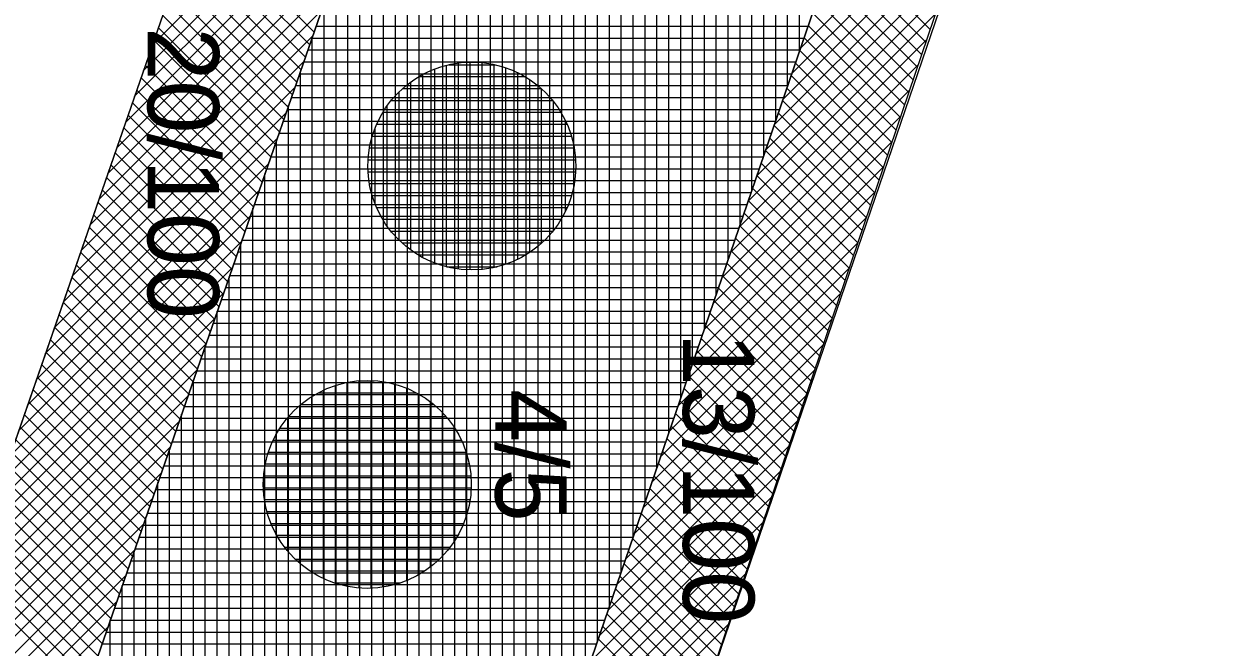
# Model space of a CAD drawing. Extents: x -565346 to -564154, y -1097386 to -1095620.
# Drawn here: x -564216.58 to -564196.4, y -1096400.96 to -1096390.47 of the extents above; entities that cross this region are included whole.
import ezdxf

# ---------------------------------------------------------------- set-up
doc = ezdxf.new("R2010")
doc.units = 0
for name, color, linetype in [('Vrstva 1', 7, 'Continuous'), ('Vrstva 13', 7, 'Continuous'), ('Vrstva 40', 7, 'Continuous'), ('Vrstva 41', 7, 'Continuous'), ('Vrstva 42', 7, 'Continuous'), ('Vrstva 43', 7, 'Continuous'), ('Vrstva 44', 7, 'Continuous')]:
    doc.layers.add(name, color=color, linetype=linetype)

msp = doc.modelspace()

# ---------------------------------------------------------------- linework, layer by layer
at = {"layer": 'Vrstva 1'}
msp.add_line((-564183.37, -1096301.17), (-564225.11, -1096421.68), dxfattribs=at)
at = {"layer": 'Vrstva 13'}
msp.add_line((-564171.03, -1096302.15), (-564215.39, -1096431.76), dxfattribs=at)
at = {"layer": 'Vrstva 41'}
for points in [[(-564215.226, -1096425.104), (-564213.26, -1096425.74), (-564190.01, -1096357.19), (-564171.03, -1096302.15), (-564177.55, -1096264.11), (-564190.98, -1096227.75), (-564194.264, -1096223.181), (-564195.888, -1096224.348), (-564192.762, -1096228.697), (-564179.49, -1096264.63), (-564173.087, -1096301.985)], [(-564225.11, -1096421.68), (-564222.748, -1096422.498), (-564180.797, -1096301.38), (-564186.765, -1096266.582), (-564199.442, -1096232.246), (-564201.974, -1096228.723), (-564204.005, -1096230.182), (-564201.67, -1096233.43), (-564189.19, -1096267.23), (-564183.37, -1096301.17)]]:
    msp.add_lwpolyline(points, close=True, dxfattribs=at)
at = {"layer": 'Vrstva 42'}
for p, q in [((-564210.378, -1096386.783), (-564214.425, -1096390.83)), ((-564210.527, -1096387.216), (-564214.575, -1096391.263)), ((-564210.677, -1096387.649), (-564214.725, -1096391.696)), ((-564200.371, -1096387.737), (-564203.512, -1096390.878)), ((-564210.827, -1096388.081), (-564214.875, -1096392.129)), ((-564200.516, -1096388.165), (-564203.659, -1096391.308)), ((-564210.977, -1096388.514), (-564215.024, -1096392.561)), ((-564213.667, -1096388.643), (-564211.702, -1096390.608)), ((-564200.661, -1096388.593), (-564203.806, -1096391.738)), ((-564213.74, -1096388.853), (-564211.775, -1096390.818)), ((-564211.127, -1096388.947), (-564215.174, -1096392.994)), ((-564213.813, -1096389.063), (-564211.848, -1096391.028)), ((-564200.806, -1096389.021), (-564203.953, -1096392.168)), ((-564202.877, -1096389.023), (-564201.331, -1096390.568)), ((-564202.949, -1096389.233), (-564201.403, -1096390.78)), ((-564211.277, -1096389.379), (-564215.324, -1096393.427)), ((-564213.886, -1096389.273), (-564211.921, -1096391.238)), ((-564200.951, -1096389.449), (-564204.101, -1096392.598)), ((-564203.021, -1096389.444), (-564201.474, -1096390.991)), ((-564213.958, -1096389.483), (-564211.993, -1096391.448)), ((-564203.093, -1096389.655), (-564201.546, -1096391.202)), ((-564211.427, -1096389.812), (-564215.474, -1096393.859)), ((-564214.031, -1096389.693), (-564212.066, -1096391.658)), ((-564201.096, -1096389.877), (-564204.248, -1096393.028)), ((-564203.165, -1096389.865), (-564201.617, -1096391.413)), ((-564214.104, -1096389.903), (-564212.139, -1096391.868)), ((-564203.237, -1096390.076), (-564201.689, -1096391.624)), ((-564211.577, -1096390.245), (-564215.624, -1096394.292)), ((-564214.177, -1096390.113), (-564212.212, -1096392.078)), ((-564214.249, -1096390.323), (-564212.284, -1096392.288)), ((-564201.242, -1096390.305), (-564204.395, -1096393.458)), ((-564203.309, -1096390.287), (-564201.761, -1096391.836)), ((-564211.727, -1096390.678), (-564215.774, -1096394.725)), ((-564214.322, -1096390.534), (-564212.357, -1096392.498)), ((-564203.382, -1096390.498), (-564201.832, -1096392.047)), ((-564214.395, -1096390.744), (-564212.43, -1096392.709)), ((-564201.387, -1096390.733), (-564204.542, -1096393.889)), ((-564203.454, -1096390.708), (-564201.904, -1096392.258)), ((-564214.468, -1096390.954), (-564212.503, -1096392.919)), ((-564203.526, -1096390.919), (-564201.976, -1096392.469)), ((-564211.876, -1096391.11), (-564215.924, -1096395.158)), ((-564214.54, -1096391.164), (-564212.576, -1096393.129)), ((-564201.532, -1096391.161), (-564204.689, -1096394.319)), ((-564203.598, -1096391.13), (-564202.047, -1096392.68)), ((-564214.613, -1096391.374), (-564212.648, -1096393.339)), ((-564203.67, -1096391.341), (-564202.119, -1096392.892)), ((-564212.026, -1096391.543), (-564216.074, -1096395.59)), ((-564214.686, -1096391.584), (-564212.721, -1096393.549)), ((-564201.677, -1096391.589), (-564204.836, -1096394.749)), ((-564203.742, -1096391.551), (-564202.191, -1096393.103)), ((-564214.759, -1096391.794), (-564212.794, -1096393.759)), ((-564203.814, -1096391.762), (-564202.262, -1096393.314)), ((-564212.176, -1096391.976), (-564216.223, -1096396.023)), ((-564214.831, -1096392.004), (-564212.867, -1096393.969)), ((-564201.822, -1096392.017), (-564204.984, -1096395.179)), ((-564203.886, -1096391.973), (-564202.334, -1096393.525)), ((-564214.904, -1096392.214), (-564212.939, -1096394.179)), ((-564203.959, -1096392.183), (-564202.405, -1096393.737)), ((-564212.326, -1096392.408), (-564216.373, -1096396.456)), ((-564214.977, -1096392.424), (-564213.012, -1096394.389)), ((-564201.967, -1096392.445), (-564205.131, -1096395.609)), ((-564204.031, -1096392.394), (-564202.477, -1096393.948)), ((-564215.05, -1096392.634), (-564213.085, -1096394.599)), ((-564204.103, -1096392.605), (-564202.549, -1096394.159)), ((-564212.476, -1096392.841), (-564216.523, -1096396.888)), ((-564215.122, -1096392.844), (-564213.158, -1096394.809)), ((-564202.113, -1096392.873), (-564205.278, -1096396.039)), ((-564204.175, -1096392.816), (-564202.62, -1096394.37)), ((-564215.195, -1096393.055), (-564213.23, -1096395.019)), ((-564204.247, -1096393.026), (-564202.692, -1096394.581)), ((-564212.626, -1096393.274), (-564216.673, -1096397.321)), ((-564215.268, -1096393.265), (-564213.303, -1096395.229)), ((-564202.258, -1096393.301), (-564205.425, -1096396.469)), ((-564204.319, -1096393.237), (-564202.764, -1096394.793)), ((-564215.341, -1096393.475), (-564213.376, -1096395.44)), ((-564204.391, -1096393.448), (-564202.835, -1096395.004)), ((-564212.776, -1096393.707), (-564216.823, -1096397.754)), ((-564215.414, -1096393.685), (-564213.449, -1096395.65)), ((-564204.463, -1096393.658), (-564202.907, -1096395.215)), ((-564215.486, -1096393.895), (-564213.521, -1096395.86)), ((-564202.403, -1096393.729), (-564205.572, -1096396.899)), ((-564204.535, -1096393.869), (-564202.979, -1096395.426)), ((-564215.559, -1096394.105), (-564213.594, -1096396.07)), ((-564204.608, -1096394.08), (-564203.05, -1096395.637)), ((-564212.926, -1096394.139), (-564216.973, -1096398.187)), ((-564215.632, -1096394.315), (-564213.667, -1096396.28)), ((-564202.548, -1096394.157), (-564205.72, -1096397.329)), ((-564204.68, -1096394.291), (-564203.122, -1096395.849)), ((-564204.752, -1096394.501), (-564203.193, -1096396.06)), ((-564213.075, -1096394.572), (-564217.123, -1096398.619)), ((-564215.705, -1096394.525), (-564213.74, -1096396.49)), ((-564202.693, -1096394.585), (-564205.867, -1096397.759)), ((-564204.824, -1096394.712), (-564203.265, -1096396.271)), ((-564215.777, -1096394.735), (-564213.812, -1096396.7)), ((-564213.225, -1096395.005), (-564217.273, -1096399.052)), ((-564215.85, -1096394.945), (-564213.885, -1096396.91)), ((-564202.838, -1096395.013), (-564206.014, -1096398.189)), ((-564204.896, -1096394.923), (-564203.337, -1096396.482)), ((-564215.923, -1096395.155), (-564213.958, -1096397.12)), ((-564204.968, -1096395.134), (-564203.408, -1096396.693)), ((-564213.375, -1096395.438), (-564217.422, -1096399.485)), ((-564215.996, -1096395.365), (-564214.031, -1096397.33)), ((-564202.984, -1096395.441), (-564206.161, -1096398.619)), ((-564205.04, -1096395.344), (-564203.48, -1096396.905)), ((-564216.068, -1096395.575), (-564214.104, -1096397.54)), ((-564205.112, -1096395.555), (-564203.552, -1096397.116)), ((-564213.525, -1096395.87), (-564217.572, -1096399.917)), ((-564216.141, -1096395.786), (-564214.176, -1096397.75)), ((-564203.129, -1096395.869), (-564206.308, -1096399.049)), ((-564205.185, -1096395.766), (-564203.623, -1096397.327)), ((-564216.214, -1096395.996), (-564214.249, -1096397.96)), ((-564205.257, -1096395.976), (-564203.695, -1096397.538)), ((-564213.675, -1096396.303), (-564217.722, -1096400.35)), ((-564216.287, -1096396.206), (-564214.322, -1096398.171)), ((-564203.274, -1096396.297), (-564206.455, -1096399.479)), ((-564205.329, -1096396.187), (-564203.766, -1096397.749)), ((-564216.359, -1096396.416), (-564214.395, -1096398.381)), ((-564205.401, -1096396.398), (-564203.838, -1096397.961)), ((-564213.825, -1096396.736), (-564217.872, -1096400.783)), ((-564216.432, -1096396.626), (-564214.467, -1096398.591)), ((-564203.419, -1096396.725), (-564206.603, -1096399.909)), ((-564205.473, -1096396.609), (-564203.91, -1096398.172)), ((-564216.505, -1096396.836), (-564214.54, -1096398.801)), ((-564205.545, -1096396.819), (-564203.981, -1096398.383)), ((-564216.578, -1096397.046), (-564214.613, -1096399.011)), ((-564205.617, -1096397.03), (-564204.053, -1096398.594)), ((-564213.975, -1096397.168), (-564218.022, -1096401.216)), ((-564216.651, -1096397.256), (-564214.686, -1096399.221)), ((-564203.564, -1096397.153), (-564206.75, -1096400.339)), ((-564205.689, -1096397.241), (-564204.125, -1096398.806)), ((-564216.723, -1096397.466), (-564214.758, -1096399.431)), ((-564205.762, -1096397.451), (-564204.196, -1096399.017)), ((-564214.125, -1096397.601), (-564218.172, -1096401.648)), ((-564216.796, -1096397.676), (-564214.831, -1096399.641)), ((-564203.709, -1096397.581), (-564206.897, -1096400.769)), ((-564205.834, -1096397.662), (-564204.268, -1096399.228)), ((-564216.869, -1096397.886), (-564214.904, -1096399.851)), ((-564205.906, -1096397.873), (-564204.34, -1096399.439)), ((-564214.274, -1096398.034), (-564218.322, -1096402.081)), ((-564216.942, -1096398.096), (-564214.977, -1096400.061)), ((-564203.855, -1096398.009), (-564207.044, -1096401.199)), ((-564205.978, -1096398.084), (-564204.411, -1096399.65)), ((-564217.014, -1096398.307), (-564215.049, -1096400.271)), ((-564206.05, -1096398.294), (-564204.483, -1096399.862)), ((-564214.424, -1096398.467), (-564218.472, -1096402.514)), ((-564217.087, -1096398.517), (-564215.122, -1096400.481)), ((-564204, -1096398.437), (-564207.191, -1096401.629)), ((-564206.122, -1096398.505), (-564204.554, -1096400.073)), ((-564217.16, -1096398.727), (-564215.195, -1096400.692)), ((-564206.194, -1096398.716), (-564204.626, -1096400.284)), ((-564214.574, -1096398.899), (-564218.621, -1096402.947)), ((-564217.233, -1096398.937), (-564215.268, -1096400.902)), ((-564204.145, -1096398.865), (-564207.339, -1096402.059)), ((-564206.266, -1096398.926), (-564204.698, -1096400.495)), ((-564217.305, -1096399.147), (-564215.341, -1096401.112)), ((-564206.339, -1096399.137), (-564204.769, -1096400.706)), ((-564214.724, -1096399.332), (-564218.771, -1096403.379)), ((-564217.378, -1096399.357), (-564215.413, -1096401.322)), ((-564204.29, -1096399.293), (-564207.486, -1096402.489)), ((-564206.411, -1096399.348), (-564204.841, -1096400.918)), ((-564206.483, -1096399.559), (-564204.913, -1096401.129)), ((-564214.874, -1096399.765), (-564218.921, -1096403.812)), ((-564217.451, -1096399.567), (-564215.486, -1096401.532)), ((-564204.435, -1096399.721), (-564207.633, -1096402.919)), ((-564217.524, -1096399.777), (-564215.559, -1096401.742)), ((-564206.555, -1096399.769), (-564204.984, -1096401.34)), ((-564204.58, -1096400.149), (-564207.78, -1096403.349)), ((-564206.627, -1096399.98), (-564205.056, -1096401.551)), ((-564215.024, -1096400.198), (-564219.071, -1096404.245)), ((-564206.699, -1096400.191), (-564205.128, -1096401.762)), ((-564206.771, -1096400.402), (-564205.199, -1096401.974)), ((-564215.174, -1096400.63), (-564219.221, -1096404.677)), ((-564204.726, -1096400.577), (-564207.927, -1096403.779)), ((-564206.843, -1096400.612), (-564205.271, -1096402.185)), ((-564206.916, -1096400.823), (-564205.342, -1096402.396))]:
    msp.add_line(p, q, dxfattribs=at)
at = {"layer": 'Vrstva 43'}
for p, q in [((-564203.53, -1096390.931), (-564203.53, -1096367.013)), ((-564203.73, -1096391.516), (-564203.73, -1096367.591)), ((-564203.93, -1096392.1), (-564203.93, -1096368.168)), ((-564204.13, -1096392.684), (-564204.13, -1096368.745)), ((-564204.33, -1096393.269), (-564204.33, -1096369.323)), ((-564204.53, -1096393.853), (-564204.53, -1096369.9)), ((-564204.73, -1096394.437), (-564204.73, -1096370.478)), ((-564204.93, -1096395.022), (-564204.93, -1096371.055)), ((-564205.13, -1096395.606), (-564205.13, -1096371.633)), ((-564205.33, -1096396.191), (-564205.33, -1096372.21)), ((-564205.53, -1096396.775), (-564205.53, -1096372.787)), ((-564205.73, -1096397.359), (-564205.73, -1096373.365)), ((-564205.93, -1096397.944), (-564205.93, -1096373.942)), ((-564206.13, -1096398.528), (-564206.13, -1096374.52)), ((-564206.33, -1096399.112), (-564206.33, -1096375.097)), ((-564206.53, -1096399.697), (-564206.53, -1096375.675)), ((-564206.73, -1096400.281), (-564206.73, -1096376.252)), ((-564206.93, -1096400.865), (-564206.93, -1096376.829)), ((-564207.13, -1096401.45), (-564207.13, -1096377.407)), ((-564207.33, -1096402.034), (-564207.33, -1096377.984)), ((-564207.53, -1096402.618), (-564207.53, -1096378.562)), ((-564207.73, -1096403.203), (-564207.73, -1096379.139)), ((-564207.93, -1096403.787), (-564207.93, -1096379.717)), ((-564208.13, -1096404.371), (-564208.13, -1096380.294)), ((-564208.33, -1096404.956), (-564208.33, -1096380.871)), ((-564208.53, -1096405.54), (-564208.53, -1096381.449)), ((-564208.73, -1096406.124), (-564208.73, -1096382.026)), ((-564208.93, -1096406.709), (-564208.93, -1096382.604)), ((-564209.13, -1096407.293), (-564209.13, -1096383.181)), ((-564209.33, -1096407.877), (-564209.33, -1096383.758)), ((-564209.53, -1096408.462), (-564209.53, -1096384.336)), ((-564209.73, -1096409.046), (-564209.73, -1096384.913)), ((-564209.93, -1096409.63), (-564209.93, -1096385.491)), ((-564210.13, -1096410.215), (-564210.13, -1096386.068)), ((-564210.33, -1096410.799), (-564210.33, -1096386.646)), ((-564210.53, -1096411.384), (-564210.53, -1096387.223)), ((-564210.73, -1096411.968), (-564210.73, -1096387.8)), ((-564210.93, -1096412.552), (-564210.93, -1096388.378)), ((-564211.13, -1096413.137), (-564211.13, -1096388.955)), ((-564211.33, -1096413.721), (-564211.33, -1096389.533)), ((-564211.53, -1096414.305), (-564211.53, -1096390.11)), ((-564211.668, -1096390.51), (-564203.386, -1096390.51)), ((-564211.738, -1096390.71), (-564203.454, -1096390.71)), ((-564211.73, -1096414.89), (-564211.73, -1096390.688)), ((-564211.807, -1096390.91), (-564203.523, -1096390.91)), ((-564211.93, -1096415.474), (-564211.93, -1096391.265)), ((-564211.876, -1096391.11), (-564203.591, -1096391.11)), ((-564211.946, -1096391.31), (-564203.66, -1096391.31)), ((-564212.015, -1096391.51), (-564203.728, -1096391.51)), ((-564212.13, -1096416.058), (-564212.13, -1096391.842)), ((-564212.084, -1096391.71), (-564203.796, -1096391.71)), ((-564212.153, -1096391.91), (-564203.865, -1096391.91)), ((-564212.223, -1096392.11), (-564203.933, -1096392.11)), ((-564212.33, -1096416.643), (-564212.33, -1096392.42)), ((-564212.292, -1096392.31), (-564204.002, -1096392.31)), ((-564212.361, -1096392.51), (-564204.07, -1096392.51)), ((-564212.43, -1096392.71), (-564204.139, -1096392.71)), ((-564212.53, -1096417.227), (-564212.53, -1096392.997)), ((-564212.5, -1096392.91), (-564204.207, -1096392.91)), ((-564212.569, -1096393.11), (-564204.276, -1096393.11)), ((-564212.638, -1096393.31), (-564204.344, -1096393.31)), ((-564212.777, -1096393.71), (-564204.481, -1096393.71)), ((-564212.73, -1096417.811), (-564212.73, -1096393.575)), ((-564212.708, -1096393.51), (-564204.413, -1096393.51)), ((-564212.846, -1096393.91), (-564204.549, -1096393.91)), ((-564212.915, -1096394.11), (-564204.618, -1096394.11)), ((-564212.985, -1096394.31), (-564204.686, -1096394.31)), ((-564212.93, -1096418.396), (-564212.93, -1096394.152)), ((-564213.054, -1096394.51), (-564204.755, -1096394.51)), ((-564213.123, -1096394.71), (-564204.823, -1096394.71)), ((-564213.192, -1096394.91), (-564204.892, -1096394.91)), ((-564213.13, -1096418.98), (-564213.13, -1096394.73)), ((-564213.262, -1096395.11), (-564204.96, -1096395.11)), ((-564213.331, -1096395.31), (-564205.029, -1096395.31)), ((-564213.33, -1096419.564), (-564213.33, -1096395.307)), ((-564213.4, -1096395.51), (-564205.097, -1096395.51)), ((-564213.47, -1096395.71), (-564205.166, -1096395.71)), ((-564213.539, -1096395.91), (-564205.234, -1096395.91)), ((-564213.53, -1096420.149), (-564213.53, -1096395.884)), ((-564213.608, -1096396.11), (-564205.302, -1096396.11)), ((-564213.677, -1096396.31), (-564205.371, -1096396.31)), ((-564213.747, -1096396.51), (-564205.439, -1096396.51)), ((-564213.73, -1096420.733), (-564213.73, -1096396.462)), ((-564213.816, -1096396.71), (-564205.508, -1096396.71)), ((-564213.885, -1096396.91), (-564205.576, -1096396.91)), ((-564213.954, -1096397.11), (-564205.645, -1096397.11)), ((-564213.93, -1096421.317), (-564213.93, -1096397.039)), ((-564214.024, -1096397.31), (-564205.713, -1096397.31)), ((-564214.093, -1096397.51), (-564205.782, -1096397.51)), ((-564214.162, -1096397.71), (-564205.85, -1096397.71)), ((-564214.13, -1096421.902), (-564214.13, -1096397.617)), ((-564214.232, -1096397.91), (-564205.919, -1096397.91)), ((-564214.301, -1096398.11), (-564205.987, -1096398.11)), ((-564214.37, -1096398.31), (-564206.055, -1096398.31)), ((-564214.33, -1096422.486), (-564214.33, -1096398.194)), ((-564214.439, -1096398.51), (-564206.124, -1096398.51)), ((-564214.509, -1096398.71), (-564206.192, -1096398.71)), ((-564214.578, -1096398.91), (-564206.261, -1096398.91)), ((-564214.53, -1096423.07), (-564214.53, -1096398.772)), ((-564214.647, -1096399.11), (-564206.329, -1096399.11)), ((-564214.73, -1096423.655), (-564214.73, -1096399.349)), ((-564214.716, -1096399.31), (-564206.398, -1096399.31)), ((-564214.786, -1096399.51), (-564206.466, -1096399.51)), ((-564214.855, -1096399.71), (-564206.535, -1096399.71)), ((-564214.93, -1096424.239), (-564214.93, -1096399.926)), ((-564214.924, -1096399.91), (-564206.603, -1096399.91)), ((-564214.994, -1096400.11), (-564206.671, -1096400.11)), ((-564215.063, -1096400.31), (-564206.74, -1096400.31)), ((-564215.132, -1096400.51), (-564206.808, -1096400.51)), ((-564215.13, -1096424.824), (-564215.13, -1096400.504)), ((-564215.201, -1096400.71), (-564206.877, -1096400.71)), ((-564215.271, -1096400.91), (-564206.945, -1096400.91))]:
    msp.add_line(p, q, dxfattribs=at)
msp.add_lwpolyline([(-564186.765, -1096266.582), (-564180.797, -1096301.38), (-564222.748, -1096422.498), (-564225.11, -1096421.68), (-564223.32, -1096427.69), (-564219.79, -1096430.8), (-564216.6, -1096431.71), (-564215.39, -1096431.76), (-564213.26, -1096425.74), (-564215.226, -1096425.104), (-564173.087, -1096301.985), (-564179.49, -1096264.63)], dxfattribs=at)
at = {"layer": 'Vrstva 44'}
for p, q in [((-564209.67, -1096394.497), (-564209.67, -1096391.23)), ((-564209.47, -1096394.56), (-564209.47, -1096391.168)), ((-564209.434, -1096391.16), (-564208.652, -1096391.16)), ((-564209.27, -1096394.599), (-564209.27, -1096391.131)), ((-564209.07, -1096394.613), (-564209.07, -1096391.116)), ((-564208.87, -1096394.604), (-564208.87, -1096391.123)), ((-564208.67, -1096394.572), (-564208.67, -1096391.155)), ((-564208.47, -1096394.516), (-564208.47, -1096391.213)), ((-564210.07, -1096394.279), (-564210.07, -1096391.448)), ((-564209.936, -1096391.36), (-564208.153, -1096391.36)), ((-564209.87, -1096394.406), (-564209.87, -1096391.323)), ((-564208.27, -1096394.433), (-564208.27, -1096391.297)), ((-564208.07, -1096394.315), (-564208.07, -1096391.41)), ((-564210.27, -1096394.112), (-564210.27, -1096391.617)), ((-564210.209, -1096391.56), (-564207.88, -1096391.56)), ((-564207.87, -1096394.161), (-564207.87, -1096391.569)), ((-564210.47, -1096393.878), (-564210.47, -1096391.851)), ((-564210.399, -1096391.76), (-564207.688, -1096391.76)), ((-564207.67, -1096393.945), (-564207.67, -1096391.783)), ((-564210.542, -1096391.96), (-564207.548, -1096391.96)), ((-564210.67, -1096393.506), (-564210.67, -1096392.222)), ((-564210.645, -1096392.16), (-564207.442, -1096392.16)), ((-564207.47, -1096393.628), (-564207.47, -1096392.104)), ((-564210.718, -1096392.36), (-564207.37, -1096392.36)), ((-564210.766, -1096392.56), (-564207.323, -1096392.56)), ((-564210.791, -1096392.76), (-564207.299, -1096392.76)), ((-564210.791, -1096392.96), (-564207.298, -1096392.96)), ((-564210.767, -1096393.16), (-564207.32, -1096393.16)), ((-564210.72, -1096393.36), (-564207.368, -1096393.36)), ((-564210.649, -1096393.56), (-564207.441, -1096393.56)), ((-564210.546, -1096393.76), (-564207.542, -1096393.76)), ((-564210.406, -1096393.96), (-564207.682, -1096393.96)), ((-564210.218, -1096394.16), (-564207.868, -1096394.16)), ((-564209.949, -1096394.36), (-564208.136, -1096394.36)), ((-564209.472, -1096394.56), (-564208.616, -1096394.56)), ((-564211.14, -1096399.94), (-564211.14, -1096396.508)), ((-564210.948, -1096396.48), (-564210.686, -1096396.48)), ((-564210.94, -1096399.967), (-564210.94, -1096396.48)), ((-564210.74, -1096399.971), (-564210.74, -1096396.477)), ((-564210.54, -1096399.953), (-564210.54, -1096396.496)), ((-564211.625, -1096396.68), (-564209.981, -1096396.68)), ((-564211.54, -1096399.81), (-564211.54, -1096396.638)), ((-564211.34, -1096399.888), (-564211.34, -1096396.56)), ((-564210.34, -1096399.911), (-564210.34, -1096396.539)), ((-564210.14, -1096399.841), (-564210.14, -1096396.606)), ((-564209.94, -1096399.744), (-564209.94, -1096396.704)), ((-564211.94, -1096399.553), (-564211.94, -1096396.895)), ((-564211.922, -1096396.88), (-564209.685, -1096396.88)), ((-564211.74, -1096399.702), (-564211.74, -1096396.746)), ((-564209.74, -1096399.612), (-564209.74, -1096396.837)), ((-564212.14, -1096399.354), (-564212.14, -1096397.096)), ((-564212.127, -1096397.08), (-564209.481, -1096397.08)), ((-564209.54, -1096399.432), (-564209.54, -1096397.016)), ((-564212.275, -1096397.28), (-564209.333, -1096397.28)), ((-564209.34, -1096399.179), (-564209.34, -1096397.268)), ((-564212.388, -1096397.48), (-564209.222, -1096397.48)), ((-564212.34, -1096399.06), (-564212.34, -1096397.389)), ((-564212.466, -1096397.68), (-564209.141, -1096397.68)), ((-564209.14, -1096398.759), (-564209.14, -1096397.683)), ((-564212.518, -1096397.88), (-564209.09, -1096397.88)), ((-564212.547, -1096398.08), (-564209.062, -1096398.08)), ((-564212.54, -1096398.439), (-564212.54, -1096398.016)), ((-564212.553, -1096398.28), (-564209.057, -1096398.28)), ((-564212.535, -1096398.48), (-564209.074, -1096398.48)), ((-564212.492, -1096398.68), (-564209.115, -1096398.68)), ((-564212.425, -1096398.88), (-564209.184, -1096398.88)), ((-564212.33, -1096399.08), (-564209.28, -1096399.08)), ((-564212.197, -1096399.28), (-564209.409, -1096399.28)), ((-564212.022, -1096399.48), (-564209.588, -1096399.48)), ((-564211.773, -1096399.68), (-564209.837, -1096399.68)), ((-564211.364, -1096399.88), (-564210.243, -1096399.88))]:
    msp.add_line(p, q, dxfattribs=at)
for centre in [(-564209.044, -1096392.864), (-564210.804, -1096398.224)]:
    msp.add_circle(centre, 1.75, dxfattribs=at)

# ---------------------------------------------------------------- texts
at = {"layer": 'Vrstva 40'}
for s, p in [('20/100', (-564214.5, -1096390.53)), ('13/100', (-564205.49, -1096395.67)), ('4/5', (-564208.65, -1096396.62))]:
    msp.add_text(s, height=1.2, rotation=270, dxfattribs=at).set_placement(p)

doc.saveas('drawing.dxf')
